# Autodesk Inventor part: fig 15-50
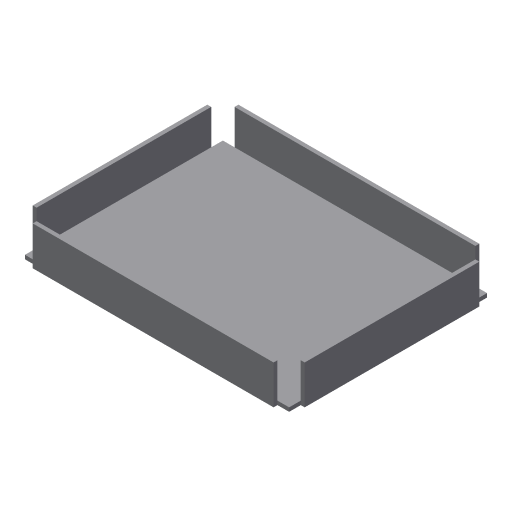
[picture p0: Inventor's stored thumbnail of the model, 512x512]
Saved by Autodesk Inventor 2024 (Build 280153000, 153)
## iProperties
Shininess: 77.0
Angle Display Precision: 2
Document Length Units: 11269
Document Angle Units: 11279
Document Time Units: 11290
Document Mass Units: 11283
Document Length Units Precision: 3
Document Angle Units Precision: 2
Compacted: True
Created: 2002-04
Part Number: fig 15-50
Document SubType Name: Sheet Metal
Density: 1 g/cm^3
Sheet Metal Rule: Default
Material: Generic
Appearance: Default
Density: 0.0
Volumn: 0.0
Area: 0.0
PropertySet Name: Model Information
Control State: 0
Master: False
Checked Out: False
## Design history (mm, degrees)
sketch "Sketch1"
  geometry: L1 (-34, 28)-(36, 28); L2 (36, 28)-(36, -24.941); L3 (36, -24.941)-(-34, -24.941); L4 (-34, -24.941)-(-34, 28)
  constraints: 8 end point, 2 parallel, 1 horizontal, 1 perpendicular
extrude "Extrusion1" join sketch "Sketch1" distance "d0" = 10; taper "d1" = 0 deg
shell "Shell1" dims "d2" = 1
feature "Corner9" dims "d27" = 4 (= CornerReliefSize), "d28" = 1 (= BendRadius), "d29" = 3, "d30" = 0, "d31" = 10, "d37" = 1 (= Thickness)
feature "Corner10" dims "d32" = 4 (= CornerReliefSize), "d33" = 1 (= BendRadius), "d34" = 3, "d35" = 0, "d36" = 10, "d37" = 1 (= Thickness)
body "Solid1"
other parameters: "Thickness" = 1, "BendRadius" = 1 (= Thickness), "BendReliefWidth" = 1 (= Thickness), "BendReliefDepth" = 0.5 (= 0.5 x Thickness), "CornerReliefSize" = 4 (= 4 x Thickness), "SeamGap" = 0.01, "MinimumRemnant" = 2 (= 2 x Thickness), "TransitionRadius" = 1 (= BendRadius), "JacobiRadiusSize" = 1 (= Thickness), "GapSize" = 1 (= Thickness)
